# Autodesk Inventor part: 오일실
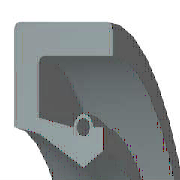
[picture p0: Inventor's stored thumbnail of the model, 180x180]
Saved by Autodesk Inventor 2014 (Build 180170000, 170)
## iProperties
IsCustomPart: 1
Company: 한국ATC센터
Created: 2009-02
Part Number: 오일실
Material: 고무
Description: 오일-실
Document SubType Name: Modeling
Standard: KS B 2804
Designer: KYOUNG IL JANG
Standards Organization: KS
Language: ko-KR
Size Designation: S - 20 32 8
Categories: <MemberInstance><Categories><Category DisplayName="샤프트 부품" InternalName="7f7aeb1f-a693-4053-b835-cee3144e0d98" Mnemonic="SHFT"><Category DisplayName="실링" Intern
Density: 0.93 g/cm^3
Mass: 1.79016 g
Surface Area: 29.931 cm^2
Volume: 1.92491 cm^3
Vendor: CBT Solutions
Appearance: 고무 - 검은색 - 버전 1.1
Author: KYOUNG IL JANG
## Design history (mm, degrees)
revolve "본체" stored, may be unused: angle "d17" = 90 deg
revolve "스프링1" stored, may be unused: angle "d18" = 90 deg
body "Solid1"
sketch "스케치1"
  geometry: L1 (0, 16)-(8, 16); L2 (8, 16)-(8, 14.75); L3 (8, 14.75)-(1.75, 14.75); L4 (0, 16)-(0, 12.1); L5 (0, 12.1)-(1.75, 11.75); L6 (1.75, 11.75)-(4.9, 10); L7 (4.9, 10)-(0, 10); L8 (6.3, 10.875)-(6.3, 12.1); L9 (0, 0)-(9.586, 0) reference; L10 (4.9, 10)-(6.3, 10.875); L11 (0, 18)-(0, -3) reference; L12 (-1.917, 0)-(11.503, 0) reference; L13 (4.2, 12.1)-(1.75, 12.59); L14 (1.75, 12.59)-(1.75, 14.75); L15 (6.3, 12.1)-(5.6, 12.1); C1 r 0.455 at (4.9, 12.1); A1 r 0.7 centre (4.9, 12.1) between (5.6, 12.1) and (4.2, 12.1)
  constraints: 26 end point, 5 horizontal alignment, 4 perpendicular, 2 centre point, 2 collinear, 2 horizontal, 2 parallel, 2 point on circle, 2 point on line, 2 vertical alignment, 1 coincident
  dimensions: "d0" = 32 diameter of L1 L9 (= SD2); "d1" = 21.75 diameter of L8.start L9 (= ABDM); "d2" = 1.25 distance of L1.end L2.end (computed from SD); "d3" = 0.91 diameter of C1 (= SPDI); "d4" = 1.4 diameter of A1 (= SPDA); "d5" = 20 diameter of L6.end L9 (= NND); "d6" = 23.5 diameter of L5.end L9 (= TKDM); "d7" = 24.2 diameter of L4.end L9 (= HLDM); "d8" = 4.9 distance from line of C1.centre L4 (= SPDST); "d9" = 6.3 distance between parallel lines of L8 L4 (= SDI); "d10" = 8 distance between parallel lines of L2 L4 (= SWDT); "d12" = 1.75 distance between parallel lines of L14 L4 (= SD)
fillet "모깎기1" dims "d11" = 0.3 (= RR)
other parameters: "SD2" = 32 [user parameter; used in 1 equation term], "SWDT" = 8 [user parameter; used in 1 equation term], "RR" = 0.3 [user parameter; used in 1 equation term], "SD" = 1.75 [user parameter; used in 2 equation terms], "NND" = 20 [user parameter; used in 1 equation term], "SPDA" = 1.4 [user parameter; used in 1 equation term], "SPDI" = 0.91 [user parameter; used in 1 equation term], "TKDM" = 23.5 [user parameter; used in 1 equation term], "HLDM" = 24.2 [user parameter; used in 1 equation term], "ABDM" = 21.75 [user parameter; used in 1 equation term], "SDI" = 6.3 [user parameter; used in 1 equation term], "SPDST" = 4.9 [user parameter; used in 1 equation term], "d13" = 0, "d14" = 0, "d15" = 0, "LAB" = 0.35 [user parameter]
